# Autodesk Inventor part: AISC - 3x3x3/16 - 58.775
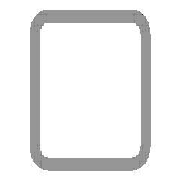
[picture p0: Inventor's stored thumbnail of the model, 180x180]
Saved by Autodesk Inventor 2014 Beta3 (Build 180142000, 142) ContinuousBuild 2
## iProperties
IsCustomPart: 1
Created: 2011-01
Part Number: AISC - 3x3x3/16 - 58.775
Material: Steel, Mild
Description: Tube
Document SubType Name: Modeling
Standard: ANSI
Designer: Beta-8540w
Standards Organization: ANSI
Language: en-US
Size Designation: 3x3x3/16
Categories: <MemberInstance><Categories><Category DisplayName="Structural Shapes" InternalName="089c4875-fa83-4c05-b084-43b9cc11f5ed" Mnemonic="GRDR"><CategoryParameter Dis
Stock Number: 3x3x3/16
Density: 7.86 g/cm^3
Appearance: Steel
_CCFamilyMember: 9
_CCFamilyDisplayName: ANSI AISC (Square) - Tube
_FrameMemberDoc: Frame Member File
_Version: 15.0.0
_GetPNFromCC: 1
G_L: 58.775 in
G_W: 3.000 in
G_H: 3.000 in
+01816D91-1541-4907-A594-A35CBE7A7E0D+CUTDETAIL1: Cut
Author: Beta-8540w
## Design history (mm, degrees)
node "Start plane"
node "End plane"
sketch "Sketch"
  geometry: L1 (-38.1, -28.575)-(-38.1, 28.575); L2 (-28.575, 38.1)-(28.575, 38.1); L3 (38.1, 28.575)-(38.1, -28.575); L4 (28.575, -38.1)-(-28.575, -38.1); L5 (-28.575, 33.337)-(28.575, 33.338); L6 (33.338, 28.575)-(33.338, -28.575); L7 (28.575, -33.337)-(-28.575, -33.338); L8 (-33.338, -28.575)-(-33.338, 28.575); L9 (0, 56.102)-(0, -56.102) reference; L10 (-56.102, 0)-(56.102, 0) reference; A1 r 9.525 centre (-28.575, -28.575) between (-38.1, -28.575) and (-28.575, -38.1); A2 r 9.525 centre (-28.575, 28.575) between (-28.575, 38.1) and (-38.1, 28.575); A3 r 9.525 centre (28.575, 28.575) between (38.1, 28.575) and (28.575, 38.1); A4 r 9.525 centre (28.575, -28.575) between (28.575, -38.1) and (38.1, -28.575); A5 r 4.763 centre (-28.575, 28.575) between (-28.575, 33.337) and (-33.338, 28.575); A6 r 4.763 centre (28.575, 28.575) between (33.338, 28.575) and (28.575, 33.338); A7 r 4.763 centre (28.575, -28.575) between (28.575, -33.337) and (33.338, -28.575); A8 r 4.763 centre (-28.575, -28.575) between (-33.338, -28.575) and (-28.575, -33.338)
  constraints: 16 end point, 16 point on circle, 8 centre point, 8 tangent, 4 parallel, 3 equal radius, 2 perpendicular, 7 other
  dimensions: "d10" = 76.2 distance between parallel lines of L2 L4 (= G_H); "d11" = 76.2 distance between parallel lines of L1 L3 (= G_W); "d12" = 4.7625 distance between parallel lines of L3 L6 (= G_T); "d15" = 38.1 distance between parallel lines of L2 L10 (= 0.5 x d10); "d16" = 38.1 distance between parallel lines of L9 L3 (= 0.5 x d11); "d17" = 9.525 radius of A1 (= G_IR)
extrude "Body" new body sketch "Sketch" stored distance "d3" = 1492.89148 (= G_L); taper "d4" = 0 deg
node "Driven Length"
  sketch "Sketch3"
    geometry: L1 (0, 0)-(10, 0) reference
    constraints: 2 end point, 1 horizontal
  workplane "Work Plane3"
  sketch "Sketch4"
    geometry: L1 (-2, 0)-(12, 0) reference; L2 (-2, 1492.891)-(12, 1492.891) reference
    dimensions: "d19" = 1492.89148 distance between parallel lines of L1 L2 (derived)
workplane "Work Plane4"
split "Split1"
body "Solid1"
other parameters: "G_W" = 76.2 [user parameter; used in 1 equation term], "G_H" = 76.2 [user parameter; used in 1 equation term], "G_T" = 4.7625 [user parameter; used in 1 equation term], "G_IR" = 9.525 [user parameter; used in 1 equation term], "G_L" = 1492.89148 (= d19) [user parameter; used in 1 equation term], "G_OFFSET_START" = 0 [user parameter; used in 1 equation term], "G_OFFSET_END" = -31.10852 [user parameter; used in 1 equation term], "d13" = 0 (computed from G_OFFSET_START), "d14" = 1492.89148 (= G_OFFSET_END + B_L), "B_L" = 1524 [user parameter; used in 1 equation term], "d18" = 90 deg
